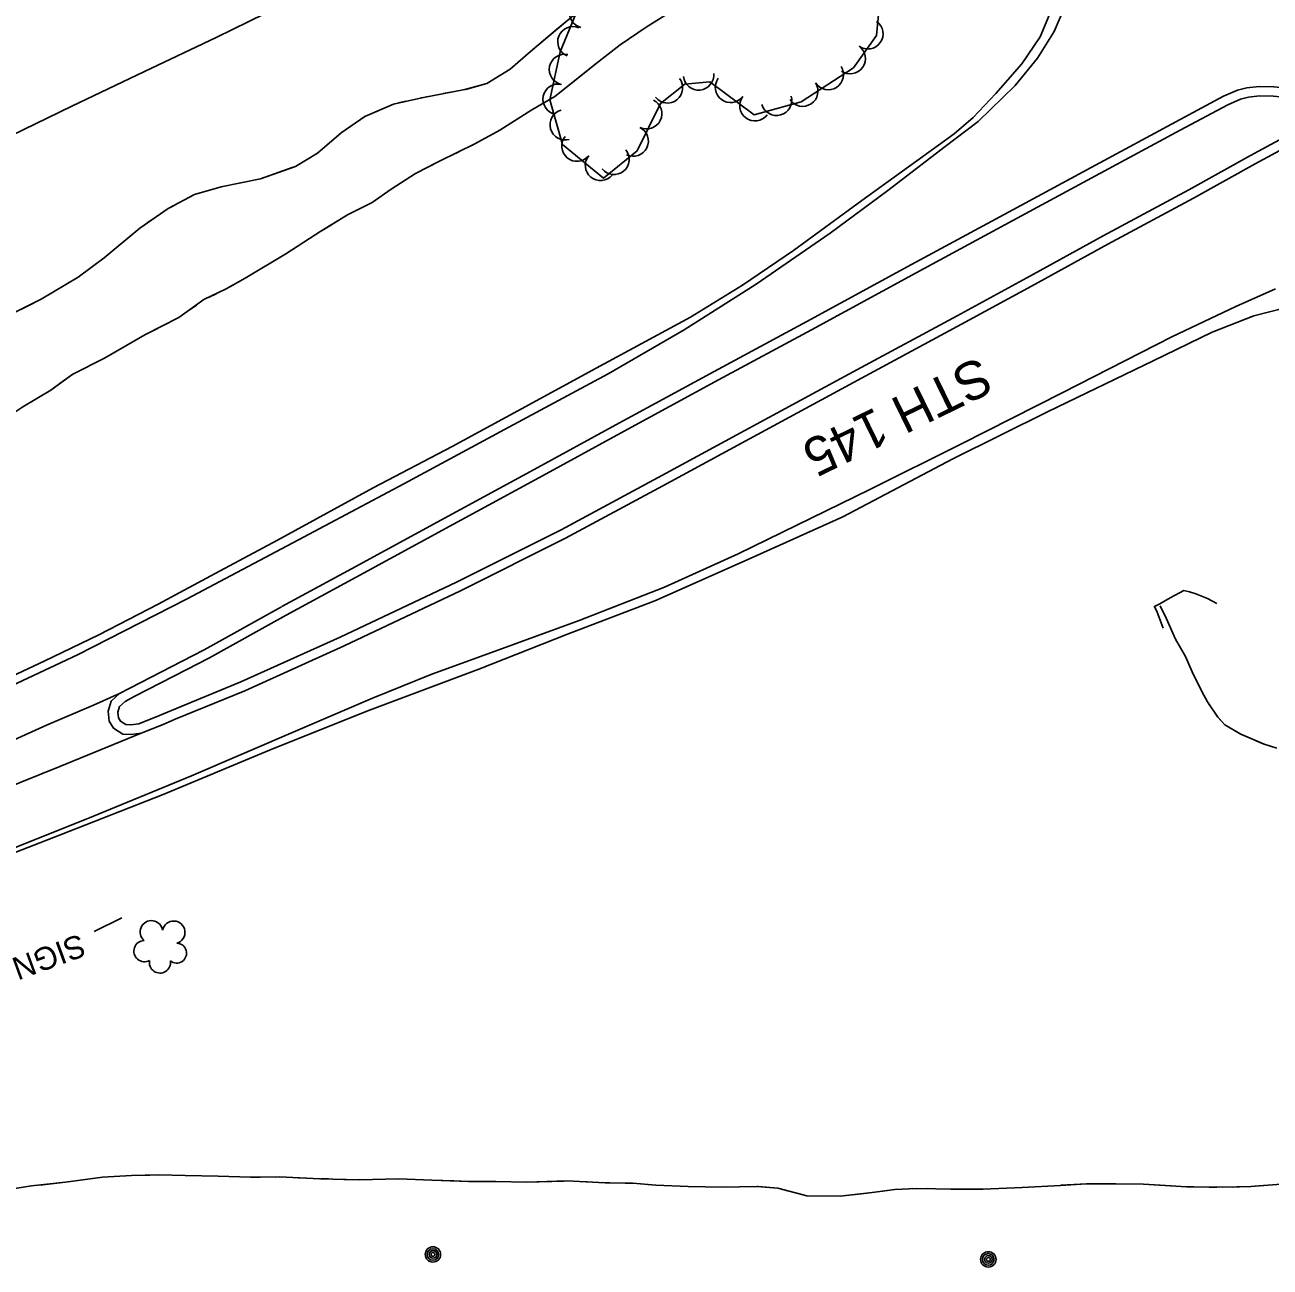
# Model space of a CAD drawing. Extents: x 353423 to 364002, y 127000 to 201942.
# Drawn here: x 358557.6 to 358884.8, y 132241.8 to 132568.3 of the extents above; entities that cross this region are included whole.
import ezdxf

# ---------------------------------------------------------------- set-up
doc = ezdxf.new("R2010")
doc.units = 0
for name, color, linetype in [('E_DTM_SlopeBottom', 7, 'Continuous'), ('E_DTM_SlopeTop', 7, 'Continuous'), ('E_FEN_Generic', 7, 'Continuous'), ('E_LAND_BrushLine', 7, 'Continuous'), ('E_MISCPROP', 7, 'Continuous'), ('E_RW_IP', 7, 'Continuous'), ('E_STRUCT_WingWall', 7, 'Continuous')]:
    doc.layers.add(name, color=color, linetype=linetype)

msp = doc.modelspace()

# ---------------------------------------------------------------- linework, layer by layer
at = {"layer": 'E_DTM_SlopeBottom'}
msp.add_lwpolyline([(358856.71, 132409.69), (358855.15, 132413.93), (358854.44, 132415.44), (358855.84, 132416.15), (358858.53, 132417.68), (358862.16, 132419.65), (358863.61, 132419.3), (358865.33, 132418.72), (358868.38, 132417.52), (358870.81, 132416.21)], dxfattribs=at)
at = {"layer": 'E_DTM_SlopeTop'}
for points in [[(358829.96, 132642.65), (358831.48, 132627.78), (358832.64, 132616.58), (358833.73, 132604.43), (358833.97, 132595.74), (358833.72, 132587.84), (358832.69, 132579.95), (358831.06, 132573.46), (358828.04, 132566.53), (358823.73, 132559.51), (358817.86, 132552.34), (358808.08, 132542.87), (358799.44, 132536.28), (358784.4, 132524.75), (358769.25, 132513.51), (358749.79, 132500.13), (358730.85, 132488.15), (358710.85, 132476.56), (358683.65, 132461.93), (358657.17, 132447.64), (358629.46, 132432.9), (358600.07, 132417.36), (358571.36, 132402.75), (358550.94, 132393.17)], [(358548.38, 132394.39), (358562.64, 132401.03), (358577.02, 132408), (358592.63, 132416.01), (358607.53, 132424.09), (358623.93, 132432.88), (358649.12, 132446.58), (358669.83, 132457.49), (358687.13, 132466.82), (358707.73, 132478.07), (358732.54, 132491.49), (358746.15, 132499.86), (358759.55, 132509.01), (358777.5, 132522.12), (358793.54, 132533.7), (358801.79, 132539.67), (358806.79, 132543.96), (358812.76, 132550.24), (358819.58, 132558.02), (358824.38, 132565.09), (358828.15, 132574.18)], [(358860.02, 132542.78), (358872.63, 132549.53), (358876.24, 132551.08), (358878.73, 132551.74), (358881.93, 132552.07), (358885.84, 132552.02), (358895.69, 132551.02), (358901.25, 132550.22), (358903.12, 132548.59), (358903.81, 132546.56), (358903.13, 132544.8), (358901.91, 132543.29), (358899.25, 132541.68), (358880.91, 132531.73)], [(358861.2, 132540.58), (358873.72, 132547.28), (358877.05, 132548.71), (358879.18, 132549.27), (358882.04, 132549.57), (358885.7, 132549.53), (358895.38, 132548.54), (358900.17, 132547.85), (358900.97, 132547.15), (358901.15, 132546.62), (358900.94, 132546.07), (358900.24, 132545.2), (358898.01, 132543.85), (358879.71, 132533.93)], [(358625.05, 132415.39), (358643.41, 132425.32), (358668.99, 132439.24), (358691.44, 132451.46), (358712.89, 132463.15), (358738.7, 132477.18), (358763.11, 132490.33), (358790.6, 132505.29), (358816.07, 132519.04), (358838.91, 132531.37), (358860.02, 132542.78)], [(358626.24, 132413.19), (358644.6, 132423.12), (358670.19, 132437.04), (358692.64, 132449.27), (358714.08, 132460.95), (358739.89, 132474.98), (358764.3, 132488.13), (358791.79, 132503.09), (358817.26, 132516.84), (358840.1, 132529.17), (358861.21, 132540.58)], [(358879.71, 132533.92), (358863.48, 132524.92), (358840.97, 132512.86), (358820.92, 132501.83), (358802.56, 132491.78), (358776.25, 132477.65), (358746.8, 132461.71), (358724.02, 132449.32), (358698.5, 132435.57), (358670.99, 132421.8), (358640.45, 132407.38), (358614.35, 132395.59), (358596.08, 132388.1), (358592.95, 132386.75), (358587.51, 132384.62), (358585.37, 132384.33), (358584.11, 132384.39), (358582.69, 132385.28), (358582.15, 132386.13), (358581.98, 132387.66), (358582.45, 132389.17), (358583.88, 132390.47), (358586.31, 132391.74), (358600.08, 132398.83), (358605.86, 132401.89), (358626.25, 132413.19)], [(358880.92, 132531.74), (358864.67, 132522.72), (358842.16, 132510.66), (358822.13, 132499.63), (358803.76, 132489.58), (358777.44, 132475.45), (358748, 132459.51), (358725.21, 132447.12), (358699.65, 132433.36), (358672.08, 132419.55), (358641.5, 132405.11), (358615.34, 132393.29), (358597.05, 132385.8), (358593.9, 132384.44), (358588.14, 132382.18), (358585.48, 132381.82), (358583.34, 132381.92), (358580.88, 132383.46), (358579.73, 132385.28), (358579.43, 132387.91), (358580.27, 132390.57), (358582.43, 132392.54), (358585.16, 132393.96), (358598.93, 132401.04), (358604.67, 132404.08), (358625.03, 132415.38)], [(358886.27, 132498.87), (358875.81, 132494.25), (358859.03, 132486.25), (358830.37, 132471.7), (358803.57, 132458.07), (358779.62, 132446.14), (358745.04, 132429.25), (358725.63, 132420.5), (358703.27, 132411.72), (358681.15, 132403.66), (358664.49, 132397.66), (358648.9, 132391.32), (358629.33, 132382.96), (358601.31, 132370.9), (358574.14, 132359.73), (358550.95, 132350.51)], [(358889.12, 132493.97), (358880.58, 132491.78), (358869.63, 132487.55), (358854.13, 132479.98), (358826.54, 132466.64), (358801.42, 132454.22), (358772.54, 132439), (358748.21, 132428.07), (358723.1, 132416.93), (358700.13, 132408.16), (358676.88, 132399), (358647.42, 132387.91), (358621.82, 132377.66), (358593.92, 132365.99), (358566.65, 132355.32), (358538.42, 132344.43)], [(358588.14, 132382.18), (358566.73, 132373.34), (358540.4, 132362.76), (358519.22, 132355.31), (358485.37, 132343.93), (358450.8, 132333.39), (358422.78, 132325.4), (358419.82, 132324.82), (358418.93, 132324.94), (358417.88, 132325.73), (358417.62, 132326.84), (358417.79, 132327.68), (358418.92, 132328.67), (358421.99, 132329.86), (358441.65, 132336.21), (358468.24, 132345.5), (358488.81, 132353.19), (358517.48, 132364.62), (358543.26, 132375.26), (358563.22, 132384.28), (358575.58, 132389.49), (358582.43, 132392.54)]]:
    msp.add_lwpolyline(points, dxfattribs=at)
at = {"layer": 'E_FEN_Generic'}
msp.add_lwpolyline([(358702.55, 132571.56), (358698.24, 132561.16), (358695.54, 132548.6), (358698.84, 132536.83), (358709.62, 132527.98), (358718.52, 132535.17), (358724.65, 132547.6), (358731.04, 132552.67), (358737.55, 132553.29), (358749.19, 132544.6), (358761.56, 132548.06), (358775.35, 132556.99), (358781.35, 132565.49), (358782.79, 132580.2)], dxfattribs=at)
for centre, radius, start, end in [((358704.69, 132571.47), 4, 75.2529, 255.2376), ((358779.1, 132565.92), 4, 234.7885, 54.7731), ((358701.6, 132563.79), 4, 67.5118, 247.4965), ((358774.48, 132559.39), 4, 234.7885, 54.7731), ((358699.39, 132556.53), 4, 77.8595, 257.8442), ((358768.72, 132555.19), 4, 212.9186, 32.9033), ((358726.45, 132551.71), 4, 218.4297, 38.4143), ((358734.63, 132555.11), 4, 185.4031, 5.3878), ((358743.02, 132551.82), 4, 143.2674, 323.2521), ((358762.01, 132550.85), 4, 212.9186, 32.9033), ((358697.71, 132548.71), 4, 77.8595, 257.8442), ((358755.11, 132548.43), 4, 195.6543, 15.639), ((358720.98, 132544.91), 4, 243.7787, 63.7633), ((358749.43, 132547.03), 4, 143.2674, 323.2521), ((358699.57, 132542), 4, 105.6704, 285.6551), ((358717.45, 132537.73), 4, 243.7787, 63.7633), ((358702.65, 132536.41), 4, 140.6245, 320.6091), ((358708.84, 132531.34), 4, 140.6245, 320.6091), ((358712.4, 132532.92), 4, 218.925, 38.9097), ((358590.81, 132329.91), 2.97, 8.541, 229.7749), ((358596.67, 132329.81), 2.97, 286.1918, 169.1651), ((358588.97, 132324.86), 2.78, 91.5119, 299.2849), ((358597.44, 132324.34), 2.61, 230.8971, 88.8297), ((358593.05, 132321.87), 2.78, 168.1889, 9.2)]:
    msp.add_arc(centre, radius, start, end, dxfattribs=at)
at = {"layer": 'E_LAND_BrushLine'}
msp.add_lwpolyline([(358575.75, 132330.04), (358583.08, 132333.63)], dxfattribs=at)
for centre, radius in [((358664.8, 132245.17), 2.02), ((358664.78, 132245.16), 1.52), ((358664.82, 132245.17), 1.01), ((358664.81, 132245.17), 0.502), ((358810.78, 132243.86), 2.02), ((358810.77, 132243.86), 1.52), ((358810.81, 132243.86), 1.01), ((358810.8, 132243.87), 0.502)]:
    msp.add_circle(centre, radius, dxfattribs=at)
at = {"layer": 'E_MISCPROP'}
msp.add_lwpolyline([(358401.35, 132465.83), (358421.21, 132475.14), (358447.67, 132488.04), (358469.88, 132498.6), (358491.87, 132509.5), (358509.27, 132517.94), (358530.2, 132527.85), (358550.67, 132537.59), (358569.86, 132546.9), (358589, 132555.99), (358607.79, 132564.98), (358625.03, 132573.36), (358635.49, 132578.04), (358639.01, 132579.73), (358643.78, 132582.85), (358652.7, 132589.43), (358657.24, 132593.33), (358660.23, 132597.03), (358665.84, 132605.99), (358673.95, 132620.21), (358675.37, 132622.86), (358675.49, 132623.86), (358675.13, 132626.43), (358673.22, 132639.8)], dxfattribs=at)
at = {"layer": 'E_STRUCT_WingWall'}
for points in [[(358697.3, 132567.03), (358699.74, 132569.08), (358706.09, 132574.3), (358712.85, 132581.74), (358718.63, 132586.59)], [(358557.01, 132467.91), (358564.35, 132472.29), (358570.12, 132476.51), (358578.46, 132480.65), (358589.1, 132486.77), (358598, 132491.35), (358604.62, 132496.07), (358610.49, 132498.9), (358615.42, 132501.74), (358626.12, 132508.08), (358635.37, 132514.05), (358642.32, 132518.37), (358648.81, 132521.59), (358653.85, 132525.1), (358660.24, 132529.2), (358666.57, 132532.47), (358675.86, 132536.99), (358682.41, 132540.6), (358690.76, 132545.91), (358696.81, 132549.46), (358707.7, 132558.08), (358713.98, 132563.02), (358720.88, 132567.68), (358727.89, 132572.06)], [(358704.55, 132555.59), (358707.7, 132558.08), (358713.98, 132563.02), (358720.88, 132567.68), (358727.89, 132572.06), (358728.18, 132572.35)], [(358554.66, 132492.6), (358561.82, 132496.14), (358571.57, 132501.93), (358578.35, 132507.04), (358587.79, 132514.84), (358595.25, 132519.99), (358602.13, 132523.7), (358609.11, 132525.74), (358619.49, 132527.8), (358628.71, 132531.04), (358634.48, 132534.54), (358640.66, 132539.88), (358646.93, 132544.15), (358654.43, 132547.46), (358661.85, 132549.11), (358673.23, 132551.27), (358678.98, 132552.88), (358685.14, 132556.65), (358690.42, 132561.27), (358699.74, 132569.08)], [(358673.41, 132551.32), (358678.98, 132552.88), (358685.14, 132556.65), (358690.42, 132561.27), (358697.3, 132567.03)], [(358680.47, 132539.53), (358682.41, 132540.6), (358690.76, 132545.91), (358696.81, 132549.46), (358704.55, 132555.59)], [(358667.52, 132550.19), (358669.48, 132550.56)], [(358627.83, 132530.74), (358628.71, 132531.04), (358634.48, 132534.54), (358640.66, 132539.88), (358646.93, 132544.15), (358652.03, 132546.4)], [(358655.77, 132547.76), (358657.72, 132548.2)], [(358661.62, 132549.06), (358661.85, 132549.11), (358663.59, 132549.44)], [(358675.2, 132536.67), (358675.86, 132536.99), (358676.97, 132537.61)], [(358669.8, 132534.05), (358671.6, 132534.92)], [(358600.1, 132522.61), (358602.13, 132523.7), (358609.11, 132525.74), (358619.49, 132527.8), (358627.83, 132530.74)], [(358664.43, 132531.37), (358666.21, 132532.29)], [(358636.12, 132514.52), (358642.32, 132518.37), (358648.81, 132521.59), (358653.85, 132525.1), (358660.24, 132529.2), (358660.88, 132529.53)], [(358594.85, 132519.72), (358595.25, 132519.99), (358596.58, 132520.71)], [(358589.91, 132516.3), (358591.56, 132517.44)], [(358585.15, 132512.66), (358586.7, 132513.93)], [(358611.38, 132499.41), (358615.42, 132501.74), (358626.12, 132508.08), (358635.37, 132514.05), (358636.12, 132514.52)], [(358557.92, 132494.21), (358561.82, 132496.14), (358571.57, 132501.93), (358578.35, 132507.04), (358582.07, 132510.11)], [(358606.01, 132496.74), (358607.81, 132497.61)], [(358533.73, 132478.59), (358541.29, 132482), (358548.87, 132487.76), (358554.66, 132492.6), (358557.92, 132494.21)], [(358600.99, 132493.48), (358602.62, 132494.64)], [(358595.93, 132490.28), (358597.71, 132491.2)], [(358567.1, 132474.3), (358570.12, 132476.51), (358578.46, 132480.65), (358589.1, 132486.77), (358592.37, 132488.45)], [(358542.66, 132458.73), (358550.11, 132463.37), (358557.01, 132467.91), (358564.35, 132472.29), (358567.1, 132474.3)], [(358855.93, 132415.59), (358857.61, 132412.18), (358860.01, 132406.86), (358862.57, 132402.27), (358864.37, 132398.25), (358866.87, 132393.1), (358868.35, 132390.41), (358871.14, 132386.37), (358872.96, 132384.35), (358877.11, 132381.91), (358883.31, 132379.23), (358886.58, 132378.19)], [(358855.93, 132415.59), (358857.61, 132412.18), (358860.01, 132406.86), (358862.57, 132402.27), (358864.37, 132398.25), (358866.87, 132393.1), (358868.35, 132390.41), (358868.86, 132389.67)], [(358871.14, 132386.38), (358871.14, 132386.37), (358872.48, 132384.89)], [(358875.78, 132382.69), (358877.11, 132381.91), (358877.53, 132381.73)], [(358881.21, 132380.14), (358883.04, 132379.35)], [(358551.07, 132261.91), (358559.32, 132263.15), (358568.23, 132264.17), (358577.93, 132265.46), (358585.56, 132265.93), (358592.74, 132266.08), (358599.7, 132265.95), (358608.33, 132265.75), (358616.84, 132265.43), (358624.46, 132265.52), (358635.04, 132265.07), (358645.44, 132264.79), (358655.8, 132265.07), (358664.48, 132264.7), (358674.16, 132264.37), (358681.34, 132264.3), (358689.52, 132264.15), (358699.98, 132264.49), (358710.11, 132263.99), (358717.34, 132263.86), (358723.41, 132263.4), (358731.86, 132262.98), (358740.82, 132262.88), (358749.9, 132263.06), (358755.46, 132262.56), (358763.06, 132260.58), (358771.85, 132260.49), (358780.27, 132261.46), (358786.18, 132262.23)], [(358561.51, 132263.4), (358568.23, 132264.17), (358577.93, 132265.46), (358585.56, 132265.93), (358590.37, 132266.03)], [(358590.37, 132266.03), (358592.74, 132266.08), (358599.7, 132265.95), (358608.33, 132265.75), (358616.84, 132265.43), (358619.36, 132265.46)], [(358623.36, 132265.51), (358624.46, 132265.52), (358625.36, 132265.48)], [(358629.35, 132265.31), (358631.35, 132265.23)], [(358635.35, 132265.06), (358637.35, 132265.01)], [(358641.35, 132264.9), (358645.44, 132264.79), (358655.8, 132265.07), (358664.48, 132264.7), (358670.33, 132264.5)], [(358670.33, 132264.5), (358674.16, 132264.37), (358681.34, 132264.3), (358689.52, 132264.15), (358699.32, 132264.46)], [(358703.32, 132264.32), (358705.32, 132264.22)], [(358709.31, 132264.03), (358710.11, 132263.99), (358711.31, 132263.97)], [(358715.31, 132263.89), (358717.31, 132263.86)], [(358721.3, 132263.56), (358723.41, 132263.4), (358731.86, 132262.98), (358740.82, 132262.88), (358749.9, 132263.06), (358750.28, 132263.03)], [(358750.28, 132263.03), (358755.46, 132262.56), (358763.06, 132260.58), (358771.85, 132260.49), (358778.96, 132261.3)], [(358782.92, 132261.8), (358784.91, 132262.06)], [(358786.18, 132262.23), (358791.91, 132262.5), (358802.15, 132262.33), (358809.39, 132262.31), (358819.69, 132262.76), (358829.77, 132263.32), (358836.62, 132263.75), (358844.3, 132263.72), (358851.54, 132263.59), (358862.83, 132262.96), (358872.4, 132262.81), (358879.8, 132263.01), (358886.6, 132263.55)], [(358788.89, 132262.36), (358790.89, 132262.45)], [(358794.89, 132262.45), (358796.89, 132262.42)], [(358800.89, 132262.36), (358802.15, 132262.33), (358809.39, 132262.31), (358819.69, 132262.76), (358829.77, 132263.32), (358829.86, 132263.33)], [(358829.86, 132263.33), (358836.62, 132263.75), (358844.3, 132263.72), (358851.54, 132263.59), (358858.84, 132263.18)], [(358862.83, 132262.96), (358864.83, 132262.93)], [(358868.83, 132262.87), (358870.83, 132262.83)], [(358874.83, 132262.87), (358876.83, 132262.93)], [(358880.83, 132263.09), (358886.6, 132263.55), (358893.95, 132263.63), (358902.47, 132263.71), (358907.75, 132263.43), (358909.73, 132262.92)]]:
    msp.add_lwpolyline(points, dxfattribs=at)

# ---------------------------------------------------------------- texts
at = {"layer": 'E_LAND_BrushLine'}
msp.add_text('SIGN', height=6, rotation=200.1174, dxfattribs=at).set_placement((358572.07, 132329.52))
at = {"layer": 'E_RW_IP'}
msp.add_text('STH 145', height=10, rotation=206.0256, dxfattribs=at).set_placement((358808.5, 132481.31))

doc.saveas('drawing.dxf')
